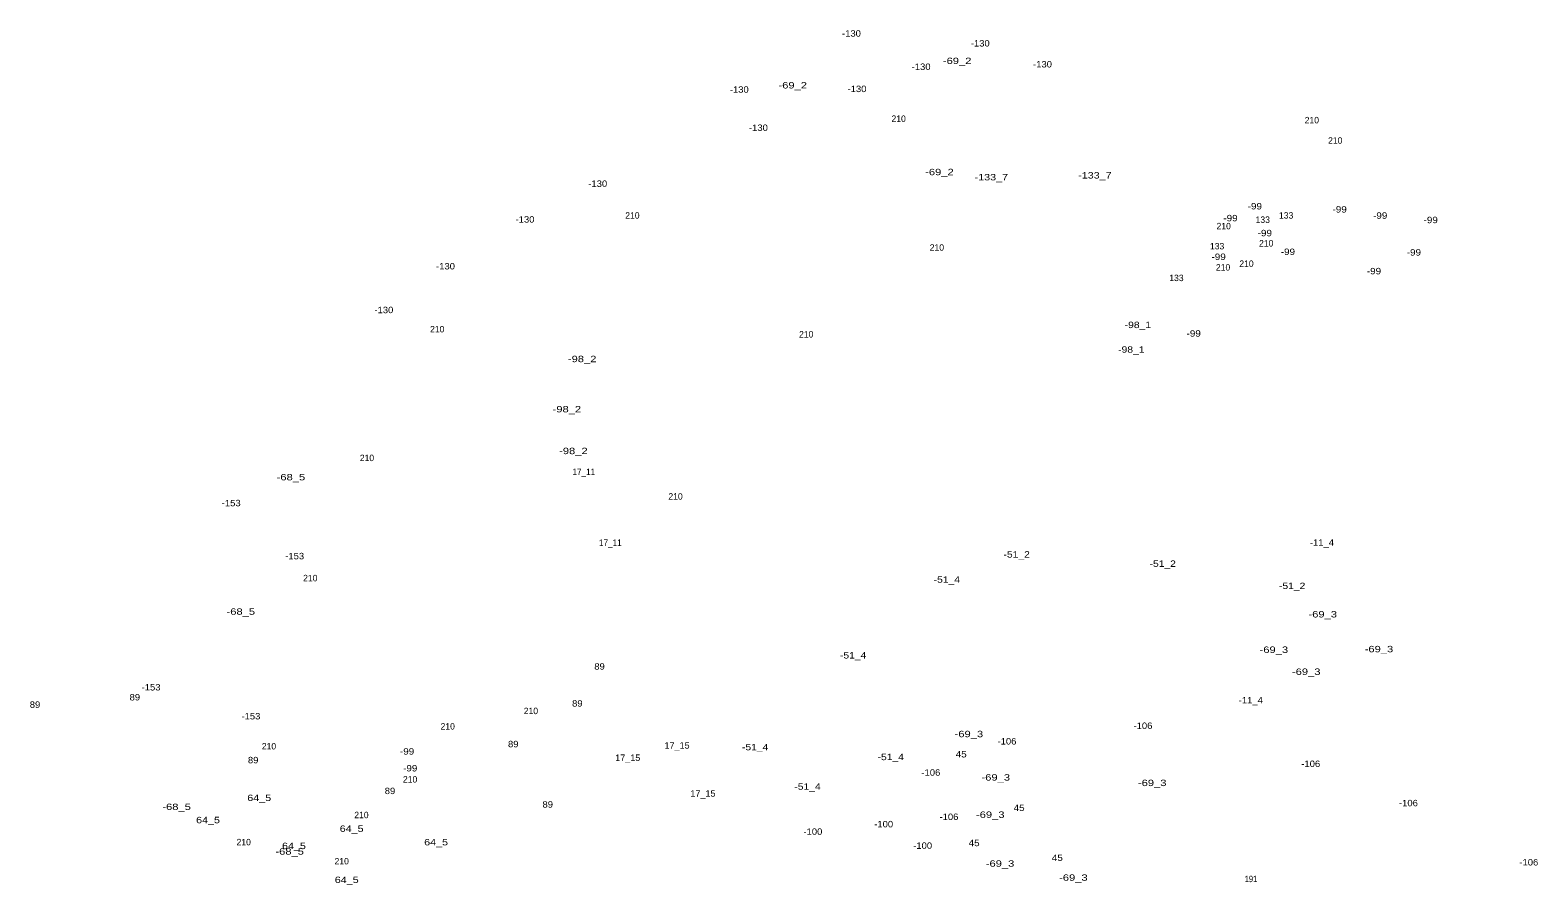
# Model space of a CAD drawing. Extents: x -662996 to -659766, y -998554 to -993949.
# Drawn here: x -660954 to -660014, y -996271 to -995738 of the extents above; entities that cross this region are included whole.
import ezdxf
from ezdxf.enums import TextEntityAlignment as Align

# ---------------------------------------------------------------- set-up
doc = ezdxf.new("R2010")
doc.units = 0
doc.header["$LTSCALE"] = 1.6
doc.layers.add('24', color=7, linetype='Continuous')

msp = doc.modelspace()

# ---------------------------------------------------------------- texts
at = {"layer": '24'}
for s, width, p in [('-130', 1.1, (-660442.16, -995742.24)), ('-130', 1.1, (-660361.9, -995748.39)), ('-69_2', 1.3, (-660376.3, -995759.32)), ('-130', 1.1, (-660398.76, -995762.99)), ('-130', 1.1, (-660323.111, -995761.45)), ('-130', 1.1, (-660512.051, -995777.2)), ('-69_2', 1.3, (-660478.74, -995774.56)), ('-130', 1.1, (-660438.701, -995776.82)), ('-130', 1.1, (-660500.14, -995801.02)), ('-69_2', 1.3, (-660387.34, -995828.65)), ('-133_7', 1.25, (-660355, -995831.85)), ('-133_7', 1.25, (-660290.48, -995830.7)), ('-130', 1.1, (-660600.25, -995835.91)), ('-99', 1.15, (-660190.819, -995849.98)), ('-99', 1.15, (-660137.959, -995851.93)), ('-130', 1.1, (-660645.571, -995858.19)), ('-99', 1.15, (-660205.98, -995857.37)), ('-99', 1.15, (-660112.699, -995855.81)), ('-99', 1.15, (-660081.22, -995858.54)), ('-99', 1.15, (-660184.6, -995866.7)), ('-99', 1.15, (-660213.37, -995881.48)), ('-99', 1.15, (-660170.22, -995878.37)), ('-99', 1.15, (-660091.709, -995878.75)), ('-130', 1.1, (-660695.111, -995887.39)), ('-99', 1.15, (-660116.579, -995890.42)), ('-130', 1.1, (-660733.51, -995914.66)), ('-98_1', 1.2, (-660263.691, -995923.96)), ('-99', 1.15, (-660228.91, -995929.3)), ('-98_2', 1.3, (-660609.96, -995945.21)), ('-98_1', 1.2, (-660267.77, -995939.32)), ('-98_2', 1.3, (-660619.49, -995976.51)), ('-98_2', 1.3, (-660615.41, -996002.56)), ('-68_5', 1.3, (-660791.44, -996018.91)), ('17_11', 0.95, (-660608.93, -996015.58)), ('-153', 1.1, (-660828.64, -996035.06)), ('17_11', 0.95, (-660592.42, -996059.75)), ('-11_4', 1.1, (-660148.99, -996059.65)), ('-153', 1.1, (-660789.081, -996068.1)), ('-51_2', 1.2, (-660339.22, -996067.07)), ('-51_2', 1.2, (-660248.199, -996072.83)), ('-51_4', 1.2, (-660382.74, -996082.73)), ('-51_2', 1.2, (-660167.559, -996086.66)), ('-68_5', 1.3, (-660822.66, -996102.72)), ('-69_3', 1.3, (-660148.5, -996104.39)), ('-51_4', 1.2, (-660441.11, -996129.98)), ('-69_3', 1.3, (-660178.97, -996126.48)), ('-69_3', 1.3, (-660113.47, -996126.1)), ('89', 1.1, (-660599.13, -996136.92)), ('-69_3', 1.3, (-660158.79, -996140.2)), ('-153', 1.1, (-660878.561, -996149.9)), ('89', 1.1, (-660950.89, -996160.74)), ('89', 1.1, (-660888.68, -996156.13)), ('89', 1.1, (-660612.96, -996159.97)), ('-11_4', 1.1, (-660193.34, -996157.99)), ('-153', 1.1, (-660816.351, -996167.96)), ('-69_3', 1.3, (-660369, -996179.05)), ('-106', 1.1, (-660260.53, -996173.89)), ('-99', 1.15, (-660719.03, -996189.9)), ('89', 1.1, (-660652.89, -996185.32)), ('17_15', 1.05, (-660550.82, -996186.15)), ('-51_4', 1.2, (-660502.169, -996187.22)), ('-106', 1.1, (-660345.26, -996183.61)), ('89', 1.1, (-660814.95, -996195.31)), ('-99', 1.15, (-660717.09, -996200.4)), ('17_15', 1.05, (-660581.54, -996193.83)), ('-51_4', 1.2, (-660417.679, -996193.36)), ('45', 1.15, (-660373.78, -996191.67)), ('-106', 1.1, (-660155.98, -996197.61)), ('-106', 1.1, (-660392.68, -996203.05)), ('-69_3', 1.3, (-660352.24, -996206.1)), ('-69_3', 1.3, (-660254.75, -996209.53)), ('64_5', 1.25, (-660811.179, -996218.86)), ('89', 1.1, (-660729.7, -996214.52)), ('17_15', 1.05, (-660534.69, -996216.11)), ('-51_4', 1.2, (-660469.53, -996211.8)), ('-68_5', 1.3, (-660862.65, -996224.47)), ('89', 1.1, (-660631.39, -996222.97)), ('45', 1.15, (-660337.689, -996225.09)), ('-106', 1.1, (-660095.11, -996222.1)), ('64_5', 1.25, (-660843.059, -996232.69)), ('64_5', 1.25, (-660753.579, -996238.07)), ('-100', 1.1, (-660422.081, -996235.24)), ('-106', 1.1, (-660381.41, -996230.66)), ('-69_3', 1.3, (-660355.67, -996229.34)), ('64_5', 1.25, (-660700.97, -996246.52)), ('-100', 1.1, (-660466.191, -996239.91)), ('45', 1.15, (-660365.72, -996246.99)), ('-68_5', 1.3, (-660792.2, -996252.28)), ('64_5', 1.25, (-660789.53, -996248.83)), ('-100', 1.1, (-660397.791, -996248.66)), ('45', 1.15, (-660313.88, -996256.21)), ('-69_3', 1.3, (-660349.57, -996259.81)), ('-106', 1.1, (-660020.1, -996259.04)), ('64_5', 1.25, (-660756.65, -996269.96)), ('-69_3', 1.3, (-660303.88, -996268.58)), ('191', 0.8, (-660193.211, -996269.42))]:
    msp.add_text(s, height=4, dxfattribs=dict(at, width=width)).set_placement(p, align=Align.CENTER)
for s, p in [('210', (-660412.74, -995795.39)), ('210', (-660155.3, -995796.28)), ('210', (-660140.71, -995808.96)), ('210', (-660578.64, -995855.71)), ('210', (-660210.21, -995862.35)), ('133', (-660185.89, -995858.37)), ('133', (-660171.299, -995855.68)), ('210', (-660388.93, -995875.68)), ('133', (-660214.309, -995874.89)), ('210', (-660183.72, -995873.11)), ('210', (-660210.6, -995888.09)), ('210', (-660196.01, -995885.79)), ('133', (-660239.65, -995894.67)), ('210', (-660700.25, -995926.62)), ('210', (-660470.34, -995929.85)), ('210', (-660744.03, -996006.91)), ('210', (-660551.76, -996030.88)), ('210', (-660779.36, -996081.82)), ('210', (-660641.88, -996164.66)), ('210', (-660693.72, -996174.27)), ('210', (-660805.09, -996186.69)), ('210', (-660717.15, -996207.31)), ('210', (-660747.49, -996229.54)), ('210', (-660820.83, -996246.44)), ('210', (-660759.78, -996258.35))]:
    msp.add_text(s, height=4, dxfattribs=at).set_placement(p, align=Align.CENTER)

doc.saveas('drawing.dxf')
